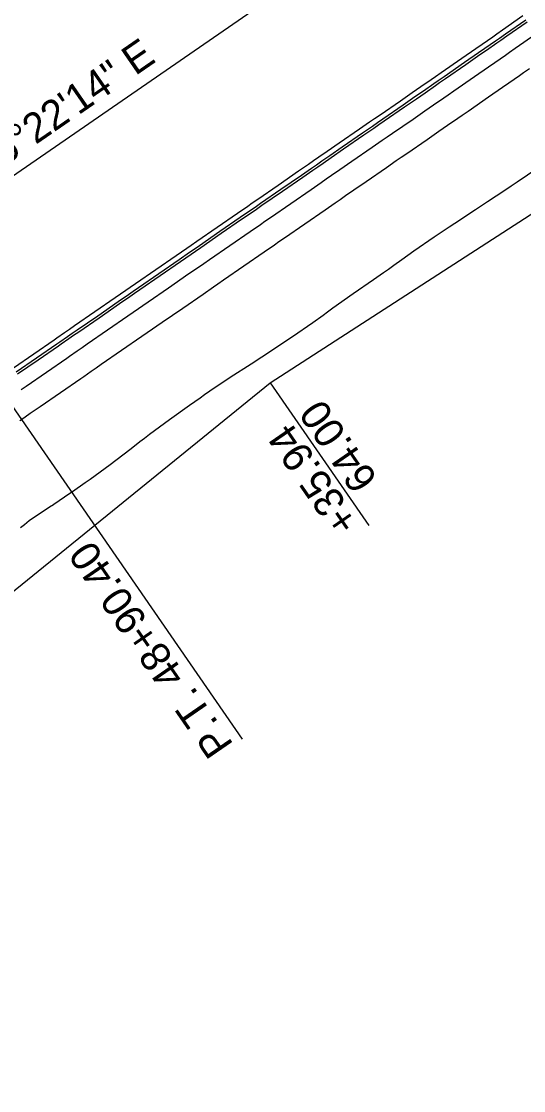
# Model space of a CAD drawing. Extents: x 1147550 to 1149124, y 2017436 to 2018779.
# Drawn here: x 1148232.5 to 1148333.9, y 2017798.5 to 2018014.6 of the extents above; entities that cross this region are included whole.
import ezdxf

# ---------------------------------------------------------------- set-up
doc = ezdxf.new("R2010")
doc.units = 0
for name, color, linetype in [('S_EDGE_CONCRETE', 7, 'Continuous'), ('S_ELECTRIC_UTILITIES', 7, 'Continuous'), ('S_MAILBOX', 7, 'Continuous'), ('S_RDW_PT_SYM', 7, 'Continuous'), ('S_SECONDARY_CTL', 7, 'Continuous'), ('S_TELEPHONE_UTILITIES', 7, 'Continuous')]:
    doc.layers.add(name, color=color, linetype=linetype)

msp = doc.modelspace()

# ---------------------------------------------------------------- linework, layer by layer
at = {"layer": 'S_EDGE_CONCRETE'}
msp.add_line((1148208.89, 2017968.31), (1148293.22, 2018026.54), dxfattribs=at)
at = {"layer": 'S_ELECTRIC_UTILITIES'}
msp.add_lwpolyline([(1148282.74, 2017941.53), (1148302.63, 2017912.73)], dxfattribs=at)
at = {"layer": 'S_MAILBOX'}
msp.add_lwpolyline([(1147623.68, 2017436.42), (1147751.67, 2017548.43), (1147958.55, 2017704.02), (1148020.45, 2017753.36), (1148124.6, 2017828.73), (1148174.25, 2017853.51), (1148282.74, 2017941.53), (1148421.63, 2018031.39), (1148612.18, 2018197.22), (1148639.91, 2018214.06), (1148753.45, 2018306.48), (1148799.03, 2018350.69)], dxfattribs=at)
at = {"layer": 'S_RDW_PT_SYM'}
msp.add_lwpolyline([(1148208.89, 2017968.31), (1148277.08, 2017869.57)], dxfattribs=at)
at = {"layer": 'S_SECONDARY_CTL'}
msp.add_lwpolyline([(1148232.31, 2017912.31), (1148233.07, 2017912.94), (1148234.06, 2017913.76), (1148238.18, 2017916.49), (1148238.95, 2017916.99), (1148239.01, 2017917.03), (1148242.29, 2017919.25), (1148242.62, 2017919.47), (1148244.4, 2017920.72), (1148245.37, 2017921.41), (1148246.38, 2017922.12), (1148250.44, 2017925.04), (1148254.4, 2017928.1), (1148254.96, 2017928.53), (1148256.43, 2017929.67), (1148257.37, 2017930.39), (1148258.36, 2017931.16), (1148262.36, 2017934.17), (1148266.45, 2017937.05), (1148268.57, 2017938.54), (1148269.46, 2017939.17), (1148270.54, 2017939.93), (1148274.68, 2017942.73), (1148278.9, 2017945.41), (1148281.06, 2017946.81), (1148281.97, 2017947.41), (1148283.09, 2017948.15), (1148287.23, 2017950.95), (1148291.35, 2017953.78), (1148293.42, 2017955.25), (1148294.32, 2017955.89), (1148295.42, 2017956.68), (1148299.5, 2017959.58), (1148303.6, 2017962.45), (1148305.62, 2017963.85), (1148306.62, 2017964.56), (1148307.69, 2017965.32), (1148309.32, 2017966.48), (1148311.76, 2017968.23), (1148315.88, 2017971.06), (1148317.9, 2017972.42), (1148318.92, 2017973.1), (1148320.04, 2017973.83), (1148324.22, 2017976.58), (1148326.63, 2017978.17), (1148328.41, 2017979.35), (1148330.53, 2017980.77), (1148331.39, 2017981.35), (1148332.6, 2017982.17), (1148336.8, 2017984.98)], dxfattribs=at)
at = {"layer": 'S_TELEPHONE_UTILITIES'}
for points in [[(1148230.86, 2017944.59), (1148234.97, 2017947.43), (1148239.09, 2017950.27), (1148239.66, 2017950.67), (1148241.2, 2017951.73), (1148242.17, 2017952.4), (1148243.2, 2017953.11), (1148247.32, 2017955.95), (1148251.43, 2017958.8), (1148253.56, 2017960.27), (1148254.46, 2017960.89), (1148255.55, 2017961.64), (1148259.66, 2017964.48), (1148263.77, 2017967.32), (1148265.89, 2017968.78), (1148266.78, 2017969.4), (1148267.89, 2017970.16), (1148272, 2017973), (1148276.12, 2017975.84), (1148278.21, 2017977.29), (1148279.12, 2017977.91), (1148280.23, 2017978.68), (1148284.35, 2017981.53), (1148288.46, 2017984.37), (1148290.48, 2017985.77), (1148291.49, 2017986.46), (1148292.57, 2017987.21), (1148294.22, 2017988.35), (1148296.69, 2017990.05), (1148300.8, 2017992.89), (1148302.81, 2017994.28), (1148303.81, 2017994.97), (1148304.92, 2017995.73), (1148309.03, 2017998.57), (1148311.4, 2018000.21), (1148313.15, 2018001.42), (1148315.24, 2018002.87), (1148316.1, 2018003.46), (1148317.29, 2018004.28), (1148321.42, 2018007.15), (1148324.25, 2018009.11), (1148325.55, 2018010.01), (1148327.68, 2018011.49), (1148328.49, 2018012.06), (1148329.68, 2018012.89), (1148333.8, 2018015.76)], [(1148231.43, 2017943.77), (1148235.54, 2017946.61), (1148239.66, 2017949.45), (1148240.23, 2017949.85), (1148241.76, 2017950.9), (1148242.74, 2017951.58), (1148243.77, 2017952.29), (1148247.89, 2017955.13), (1148252, 2017957.97), (1148254.13, 2017959.44), (1148255.03, 2017960.06), (1148256.11, 2017960.81), (1148260.23, 2017963.66), (1148264.34, 2017966.5), (1148266.45, 2017967.95), (1148267.35, 2017968.58), (1148268.46, 2017969.34), (1148272.57, 2017972.18), (1148276.69, 2017975.02), (1148278.77, 2017976.46), (1148279.68, 2017977.09), (1148280.8, 2017977.86), (1148284.91, 2017980.7), (1148289.03, 2017983.54), (1148291.05, 2017984.94), (1148292.06, 2017985.64), (1148293.14, 2017986.39), (1148294.79, 2017987.52), (1148297.26, 2017989.23), (1148301.37, 2017992.07), (1148303.38, 2017993.45), (1148304.38, 2017994.15), (1148305.48, 2017994.91), (1148309.6, 2017997.75), (1148311.97, 2017999.39), (1148313.72, 2018000.6), (1148315.81, 2018002.04), (1148316.67, 2018002.63), (1148317.86, 2018003.46), (1148321.99, 2018006.33), (1148324.82, 2018008.29), (1148326.12, 2018009.19), (1148328.25, 2018010.67), (1148329.06, 2018011.24), (1148330.25, 2018012.07), (1148334.38, 2018014.94)], [(1148231.71, 2017943.35), (1148235.83, 2017946.2), (1148239.94, 2017949.04), (1148240.52, 2017949.43), (1148242.05, 2017950.49), (1148243.03, 2017951.17), (1148244.06, 2017951.88), (1148248.17, 2017954.72), (1148252.28, 2017957.56), (1148254.41, 2017959.03), (1148255.31, 2017959.65), (1148256.4, 2017960.4), (1148260.51, 2017963.24), (1148264.63, 2017966.09), (1148266.74, 2017967.54), (1148267.64, 2017968.16), (1148268.74, 2017968.93), (1148272.86, 2017971.77), (1148276.97, 2017974.61), (1148279.06, 2017976.05), (1148279.97, 2017976.68), (1148281.08, 2017977.45), (1148285.2, 2017980.29), (1148289.31, 2017983.13), (1148291.34, 2017984.53), (1148292.34, 2017985.23), (1148293.43, 2017985.97), (1148295.07, 2017987.11), (1148297.54, 2017988.82), (1148301.65, 2017991.66), (1148303.66, 2017993.04), (1148304.67, 2017993.74), (1148305.77, 2017994.5), (1148309.88, 2017997.34), (1148312.26, 2017998.98), (1148314.01, 2018000.19), (1148316.1, 2018001.63), (1148316.95, 2018002.22), (1148318.14, 2018003.05), (1148322.28, 2018005.91), (1148325.1, 2018007.88), (1148326.41, 2018008.78), (1148328.54, 2018010.26), (1148329.34, 2018010.83), (1148330.54, 2018011.66), (1148334.66, 2018014.53)], [(1148232.41, 2017940.19), (1148233.42, 2017940.89), (1148237.53, 2017943.73), (1148241.65, 2017946.57), (1148242.22, 2017946.97), (1148243.75, 2017948.02), (1148244.73, 2017948.7), (1148245.76, 2017949.41), (1148249.87, 2017952.25), (1148253.99, 2017955.09), (1148256.12, 2017956.56), (1148257.02, 2017957.18), (1148258.1, 2017957.93), (1148262.22, 2017960.78), (1148266.33, 2017963.62), (1148268.44, 2017965.07), (1148269.34, 2017965.7), (1148270.45, 2017966.46), (1148274.56, 2017969.3), (1148278.67, 2017972.14), (1148280.76, 2017973.58), (1148281.67, 2017974.21), (1148282.79, 2017974.98), (1148286.9, 2017977.82), (1148291.02, 2017980.66), (1148293.04, 2017982.06), (1148294.05, 2017982.76), (1148295.13, 2017983.51), (1148296.78, 2017984.64), (1148299.25, 2017986.35), (1148303.36, 2017989.19), (1148305.37, 2017990.57), (1148306.37, 2017991.27), (1148307.47, 2017992.03), (1148311.59, 2017994.87), (1148313.96, 2017996.51), (1148315.71, 2017997.72), (1148317.8, 2017999.17), (1148318.66, 2017999.76), (1148319.85, 2018000.58), (1148323.99, 2018003.45), (1148326.81, 2018005.41), (1148328.12, 2018006.32), (1148330.25, 2018007.8), (1148331.06, 2018008.36), (1148332.25, 2018009.19), (1148336.38, 2018012.07)], [(1148232.15, 2017933.93), (1148232.48, 2017934.16), (1148234.27, 2017935.4), (1148235.25, 2017936.07), (1148236.26, 2017936.77), (1148240.37, 2017939.61), (1148244.49, 2017942.45), (1148245.06, 2017942.85), (1148246.59, 2017943.91), (1148247.57, 2017944.58), (1148248.6, 2017945.3), (1148252.72, 2017948.14), (1148256.83, 2017950.98), (1148258.96, 2017952.45), (1148259.86, 2017953.07), (1148260.94, 2017953.82), (1148265.06, 2017956.66), (1148269.17, 2017959.5), (1148271.28, 2017960.96), (1148272.18, 2017961.58), (1148273.29, 2017962.34), (1148277.4, 2017965.18), (1148281.52, 2017968.03), (1148283.6, 2017969.47), (1148284.51, 2017970.1), (1148285.63, 2017970.87), (1148289.74, 2017973.71), (1148293.86, 2017976.55), (1148295.88, 2017977.95), (1148296.89, 2017978.64), (1148297.97, 2017979.39), (1148299.62, 2017980.53), (1148302.09, 2017982.23), (1148306.2, 2017985.07), (1148308.21, 2017986.46), (1148309.21, 2017987.15), (1148310.31, 2017987.92), (1148314.43, 2017990.76), (1148316.8, 2017992.4), (1148318.56, 2017993.61), (1148320.65, 2017995.05), (1148321.5, 2017995.65), (1148322.7, 2017996.47), (1148326.84, 2017999.34), (1148329.67, 2018001.3), (1148330.97, 2018002.21), (1148333.1, 2018003.7), (1148333.91, 2018004.26), (1148335.11, 2018005.09)]]:
    msp.add_lwpolyline(points, dxfattribs=at)

# ---------------------------------------------------------------- texts
at = {"layer": 'S_ELECTRIC_UTILITIES'}
for s, p in [('64.00', (1148304.64, 2017922.13)), ('+35.94', (1148300.94, 2017913.41))]:
    msp.add_text(s, height=6, rotation=124.6295, dxfattribs=at).set_placement(p)
at = {"layer": 'S_RDW_PT_SYM'}
for s, rotation, p in [('N 55%%d22\'14" E', 34.6295, (1148218.77, 2017978.17)), ('P.T. 48+90.40', 124.6295, (1148275.44, 2017868.43))]:
    msp.add_text(s, height=6, rotation=rotation, dxfattribs=at).set_placement(p)

doc.saveas('drawing.dxf')
